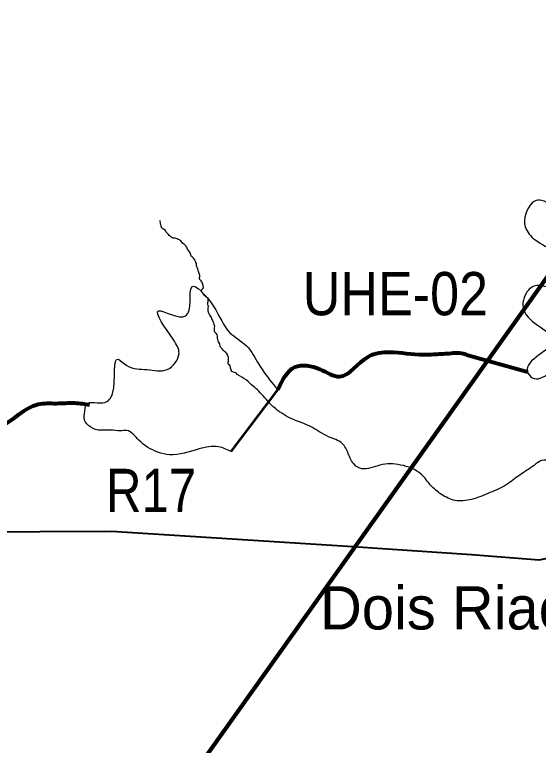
# Model space of a CAD drawing. Extents: x 553962 to 842807, y 8883888 to 9032388.
# Drawn here: x 703290 to 709342, y 8959086 to 8967533 of the extents above; entities that cross this region are included whole.
import ezdxf
from ezdxf.enums import TextEntityAlignment as Align

# ---------------------------------------------------------------- set-up
doc = ezdxf.new("R2010")
doc.units = 0
doc.header["$LTSCALE"] = 200
for name, color, linetype, lineweight in [('12', 7, 'Continuous', 25), ('24', 7, 'Continuous', 25), ('50', 7, 'Continuous', 80), ('51', 7, 'Continuous', 25), ('9', 7, 'Continuous', 90)]:
    doc.layers.add(name, color=color, linetype=linetype, lineweight=lineweight)
doc.layers.add('41', color=7, linetype='Continuous')
doc.layers.add('53', color=7, linetype='Continuous')

msp = doc.modelspace()

# ---------------------------------------------------------------- linework, layer by layer
at = {"layer": '12', "lineweight": 40}
for points in [[(693487.4, 8962819.8), (696836.9, 8961144.8), (697384.1, 8960961.8), (697603.7, 8960973.6), (697714.4, 8961082.3), (698321.2, 8961447.4), (698679, 8961567.8), (700187.3, 8961472.5), (701093.5, 8961547), (704410.2, 8961560.7)], [(704410.2, 8961560.7), (707197.4, 8961384.6), (708568.6, 8961290.5), (709350.1, 8961228.9), (709812.8, 8961324.8)]]:
    msp.add_lwpolyline(points, dxfattribs=at)
at = {"layer": '24'}
for points in [[(705462, 8964317), (705454, 8964323.8), (705449.7, 8964336.7), (705451.5, 8964350), (705458.7, 8964361.9), (705468.1, 8964370.6), (705473.4, 8964382.4), (705470.6, 8964396.2), (705466.6, 8964409.2), (705463.8, 8964422), (705458.7, 8964433.7), (705454.1, 8964445.5), (705446.7, 8964456.5), (705436.3, 8964463.7), (705427.9, 8964475.5), (705427.5, 8964488.9), (705430.3, 8964502), (705430.9, 8964516), (705426.8, 8964529), (705424.1, 8964541.7), (705419.9, 8964553.7), (705415.7, 8964565.5), (705411.4, 8964578.6), (705408.1, 8964592.5), (705401.5, 8964603.7), (705395.9, 8964616.2), (705392.6, 8964629.3), (705391.6, 8964643), (705390.5, 8964656.5), (705385.8, 8964668.8), (705380.1, 8964681.2), (705374, 8964692.3), (705367.4, 8964703.5), (705359.7, 8964714.5), (705350.4, 8964723.6), (705340.7, 8964731.8), (705331.4, 8964740.9), (705324.3, 8964754.5), (705324.1, 8964767.8), (705318.9, 8964779.2), (705311.5, 8964790.4), (705302.1, 8964801.5), (705294.8, 8964811.6), (705289.5, 8964823), (705282.6, 8964834.3), (705277.5, 8964846), (705270.7, 8964857.2), (705262.2, 8964867.1), (705252.3, 8964876.4), (705240.9, 8964883.8), (705231.1, 8964892.9), (705222.1, 8964902.5), (705213.5, 8964912.7), (705203.7, 8964921.9), (705193.6, 8964930.3), (705180.4, 8964933.5), (705169.9, 8964940.5), (705158.2, 8964945), (705145.8, 8964948.7), (705132.4, 8964948.5), (705119.9, 8964950.6), (705108.2, 8964956.4), (705096.8, 8964963.6), (705087, 8964971.5), (705077.6, 8964979.9), (705068.8, 8964989.5), (705059.7, 8964999.7), (705050, 8965008.9), (705041.6, 8965019.5), (705036.2, 8965031.3), (705028.3, 8965041.6), (705016.9, 8965048.5), (705002.3, 8965055.8), (704992.8, 8965064.7), (704987, 8965075.9), (704982.4, 8965089.2), (704979.4, 8965101.5), (704977.2, 8965114.3), (704976.5, 8965127.2), (704973.7, 8965140.4), (704971.5, 8965153.2)], [(705796.9, 8963407.8), (705795.2, 8963421.2), (705789.1, 8963433), (705785.2, 8963445.2), (705783.8, 8963459), (705780, 8963472), (705772.6, 8963483.1), (705760.6, 8963488.6), (705755.9, 8963500.6), (705757.4, 8963514.6), (705760.4, 8963528.5), (705761.4, 8963541.1), (705760.8, 8963554.2), (705759.6, 8963568.1), (705757, 8963581.3), (705752.5, 8963594.8), (705746.6, 8963607), (705738.4, 8963618.3), (705729.5, 8963628), (705719.6, 8963636.3), (705708.3, 8963645.6), (705699.3, 8963655.2), (705688, 8963668.5), (705678.7, 8963678.5), (705670.9, 8963689.6), (705664.2, 8963701.2), (705661.4, 8963714.8), (705660.1, 8963727.5), (705654.2, 8963738.9), (705646.7, 8963751.8), (705640.5, 8963763.2), (705636.3, 8963775.9), (705634.8, 8963790.6), (705634.1, 8963803.8), (705632.8, 8963816.8), (705630.1, 8963830.7), (705623.7, 8963841.5), (705613.4, 8963851), (705604.1, 8963861.6), (705599.9, 8963874.2), (705599.2, 8963887.2), (705599.7, 8963900.5), (705601, 8963913.1), (705601.7, 8963926), (705599.6, 8963938.6), (705595.6, 8963951.5), (705590.5, 8963965.1), (705583.9, 8963980.3), (705579.5, 8963992.5), (705575.1, 8964004.7), (705569.2, 8964017.7), (705563.2, 8964031.1), (705556.4, 8964042.2), (705548.9, 8964054.6), (705541.1, 8964066.9), (705534.2, 8964082.5), (705529.1, 8964094.5), (705524.9, 8964106.6), (705524.7, 8964120.3), (705525.7, 8964132.8), (705527.2, 8964145.2), (705528.9, 8964158.3), (705528.4, 8964172.5), (705524.4, 8964184.8), (705523.4, 8964198.4), (705523.4, 8964204.9), (705525.6, 8964217.9), (705528, 8964230.7), (705526, 8964243.7), (705520.9, 8964255.5), (705512.5, 8964265), (705501.2, 8964271.4), (705490.1, 8964278.3), (705480.6, 8964288), (705474.5, 8964299), (705470.1, 8964311.2)]]:
    msp.add_lwpolyline(points, dxfattribs=at)
msp.add_spline([(710131.8, 8961656.3), (710038.2, 8961644.6), (709952.5, 8961734.3), (709819.9, 8961831.8), (709687.4, 8961917.5), (709656.2, 8962018.9), (709609.4, 8962151.4), (709543.1, 8962295.7), (709476.8, 8962369.8), (709379.4, 8962377.6), (709293.6, 8962323), (709126, 8962209.9), (708970, 8962096.9), (708782.9, 8962007.2), (708568.5, 8961929.2), (708381.3, 8961917.5), (708221.5, 8961987.7), (708096.8, 8962093), (707991.5, 8962217.7), (707749.8, 8962326.9), (707512, 8962326.9), (707301.5, 8962284), (707215.7, 8962330.8), (707145.5, 8962459.4), (707075.3, 8962576.4), (706915.5, 8962654.3), (706724.5, 8962763.5), (706475, 8962868.8), (706285.5, 8962993.6), (706252.3, 8963024.5), (706110.5, 8963180), (706048.8, 8963234.9), (705965.3, 8963310.3), (705863.5, 8963374.4), (705840.7, 8963390.4), (705796.9, 8963407.8)], degree=3, dxfattribs=at)
at = {"layer": '50'}
msp.add_line((708509.8, 8963602.2), (709216.9, 8963404.4), dxfattribs=at)
for points in [[(706331.1, 8963196.6), (706530.8, 8963460.3), (706816.5, 8963435), (707042.3, 8963348.7), (707377.4, 8963582), (707622.8, 8963632.7), (708013.7, 8963602.3), (708129, 8963607.3), (708309.3, 8963617.5), (708499.8, 8963607.3), (708509.8, 8963602.2)], [(701555.7, 8962741.4), (701698, 8962420.9), (701718.7, 8962162.2), (702054.1, 8962299.1), (702364, 8962573), (702719.5, 8962694.7), (703135.2, 8962775.8), (703560.4, 8963029.4), (703770.9, 8963039.5), (703986.3, 8963044.6), (704156.8, 8963024.3)]]:
    msp.add_spline(points, degree=3, dxfattribs=at)
at = {"layer": '51', "lineweight": 53}
msp.add_line((705791.9, 8962481.6), (706331.1, 8963196.6), dxfattribs=at)
at = {"layer": '51'}
msp.add_line((706331.1, 8963196.6), (705791.9, 8962481.6), dxfattribs=at)
for points in [[(711709.8, 8966193.7), (711785.5, 8965995.9), (711421.8, 8965227.1), (711348.1, 8965197.6), (711267.2, 8965396.5), (711112.5, 8965484.9), (710906.4, 8965433.3), (710943.2, 8965337.6), (710911.2, 8965017.1), (710961.9, 8964819.3), (710225.9, 8964581), (710206.6, 8964317.3), (709964, 8964276.7), (710000.5, 8964545.5), (710100, 8964819.3), (710177.5, 8965197.6), (710022.9, 8965418.6), (709834, 8964986.7), (709684.3, 8965123.9), (709294.1, 8965374.4), (709183.6, 8965116.5), (709267.8, 8964961.4), (709669.6, 8964621.6), (709610.7, 8964468.2), (709507.6, 8964387.2), (709479.8, 8964383.2), (709304.4, 8964398.5), (709204.4, 8964317.3), (709185, 8964089.1), (709522.3, 8963753.6), (709216.9, 8963404.4), (709272, 8963333.7), (709467.5, 8963384.1)], [(705791.9, 8962481.6), (705646.4, 8962537.3), (705421, 8962512), (705081.3, 8962445.8), (704945, 8962476.5), (704727.2, 8962613.2), (704583.5, 8962725), (704510.8, 8962721.4), (704402.5, 8962731.3), (704255, 8962731.3), (704092, 8962872.1), (704096.9, 8962917.8), (704120.3, 8963028.6), (704332.1, 8963049.6), (704422.2, 8963154.6), (704491.1, 8963548.4), (704586.5, 8963475.6), (704822.1, 8963430), (705051.8, 8963430.2), (705189.6, 8963617.3), (705121.8, 8963779.9), (704953.5, 8964109.5), (705268.3, 8964050.4), (705337.1, 8964385.1), (705583.1, 8964168.6), (705778.1, 8963855.9), (705968.9, 8963703.8), (706114.8, 8963485.7), (706280.8, 8963257.5), (706331.1, 8963196.6)]]:
    msp.add_spline(points, degree=3, dxfattribs=at)
at = {"layer": '9'}
msp.add_lwpolyline([(691582, 8951218.7), (697371.2, 8956056), (705081.2, 8958366.8), (713138.6, 8969695)], dxfattribs=at)

# ---------------------------------------------------------------- texts
at = {"layer": '41'}
msp.add_text('Dois Riachos', height=500, dxfattribs=at).set_placement((706819.1, 8960425.8))
at = {"layer": '53'}
for s, width, p in [('UHE-02', 0.9, (707690.2, 8964057.7)), ('R17', 0.85, (704867.2, 8961782.9))]:
    msp.add_text(s, height=500, dxfattribs=dict(at, width=width)).set_placement(p, align=Align.CENTER)

doc.saveas('drawing.dxf')
